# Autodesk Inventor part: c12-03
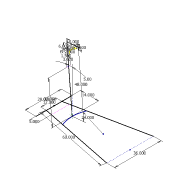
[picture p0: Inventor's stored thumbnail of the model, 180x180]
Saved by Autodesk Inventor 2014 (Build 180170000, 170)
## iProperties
Created: 2010-12
Part Number: c12-03
Material: Generic
Document SubType Name: Modeling
Designer: Thom Tremblay
Density: 1 g/cm^3
Appearance: Generic
Author: Thom Tremblay
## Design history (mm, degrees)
sketch "Sketch1"
  geometry: L1 (355.6, 0)-(-355.6, 0); L2 (152.4, 0)-(457.2, 1493.209); L3 (-152.4, 0)-(-457.2, 1493.209); L4 (224.987, 355.6)-(-224.987, 355.6); L5 (457.2, 1493.209)-(-457.2, 1493.209); L6 (-178.324, 127)-(178.324, 127); A1 r 609.6 centre (0, 965.2) between (-234.567, 402.536) and (234.567, 402.536); 4 further points
  constraints: 12 end point, 8 point on line, 3 midpoint, 3 parallel, 2 point on circle, 2 vertical alignment, 1 centre point, 1 coincident, 1 equal length, 1 horizontal, 1 horizontal alignment, 1 tangent
  dimensions: "d0" = 711.2 distance of L1.start L1.end; "d1" = 1524 distance of L2.start L2.end; "d2" = 304.8 distance of L3.start L2.start; "d3" = 355.6 distance between parallel lines of L1 L4; "d4" = 914.4 distance of L2.end L3.end; "d8" = 127 distance between parallel lines of L6 L1; "d19" = 609.6 radius of A1
sketch "Sketch2"
  geometry: L1 (355.6, 0)-(355.6, 346.923); L2 (355.6, 0)-(249.34, 1214.561); L3 (249.34, 1214.561)-(502.373, 1236.698); L4 (303.898, 1028.106)-(300.387, 1068.232); L5 (306.233, 1086.772)-(385.066, 1180.722); L6 (402.31, 1189.698)-(442.435, 1193.209); A1 r 25.4 centre (325.691, 1070.446) between (306.233, 1086.772) and (300.387, 1068.232); A2 r 25.4 centre (404.523, 1164.395) between (402.31, 1189.698) and (385.066, 1180.722); 3 further points
  constraints: 12 end point, 4 point on circle, 4 point on line, 4 tangent, 2 centre point, 2 parallel, 1 equal radius, 1 perpendicular, 1 vertical
  dimensions: "d5" = 1219.2 distance of L1.start L2.end; "d6" = 5 deg angle of L2 L1; "d11" = 254 distance of L2.end L3.end; "d12" = 50.8 distance of L4.start point (299.47, 1078.713) (= d13); "d13" = 50.8 distance of point (391.829, 1188.781) L6.end; "d14" = 25.4 radius of A1; "d15" = 45 deg angle of L5 L4; "d16" = 152.4 distance from line of L6 L4.start; "d17" = 38.1 distance between parallel lines of L3 L6; "d18" = 38.1 distance between parallel lines of L2 L4
workplane "Work Plane1"
sketch "Sketch3"
  geometry: L1 (224.987, 0)-(224.987, 1219.2) reference; L2 (186.887, 812.8)-(263.087, 812.8); 2 further points
  constraints: 2 end point, 1 midpoint, 1 perpendicular, 1 point on line
  dimensions: "d9" = 76.2 distance of L2.start L2.end; "d10" = 812.8 distance from line of L1.start L2
other parameters: "d16" = 152.4
